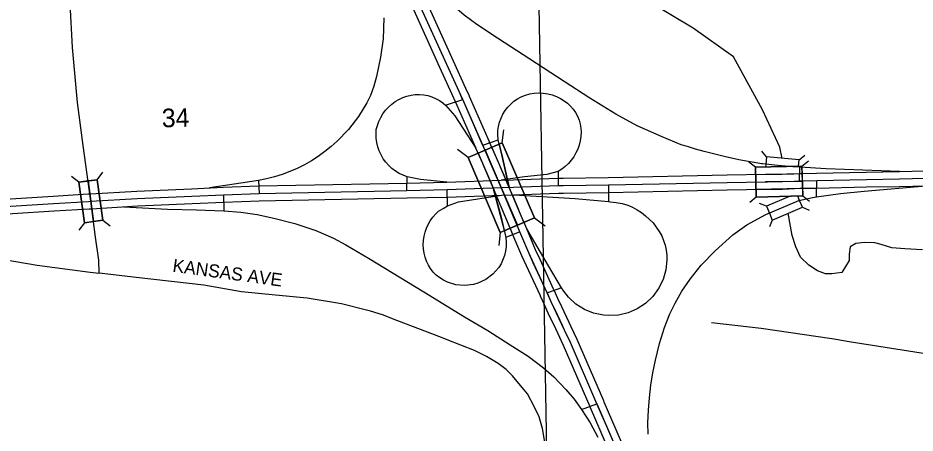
# Model space of a CAD drawing. Extents: x 281.94 to 289.14, y 116.09 to 120.89.
# Drawn here: x 285.132 to 286.097, y 117.681 to 118.127 of the extents above; entities that cross this region are included whole.
import ezdxf

# ---------------------------------------------------------------- set-up
doc = ezdxf.new("R2010")
doc.units = 0
for name, color, linetype in [('tdCiAdjCityStreetCL', 7, 'Continuous'), ('tdCiCityStreetCL', 7, 'Continuous'), ('tdCiCityStreetTxt', 7, 'Continuous'), ('tdCiCorpBndry', 7, 'Continuous'), ('tdCiCorpBndryPart', 7, 'Continuous'), ('tdCiHydroRiver', 7, 'Continuous'), ('tdCiInt', 7, 'Continuous'), ('tdCiIntCL', 7, 'Continuous'), ('tdCiIntRamp', 7, 'Continuous'), ('tdCiIntRampCL', 7, 'Continuous'), ('tdCiPriCL', 7, 'Continuous'), ('tdCiPriDiv', 7, 'Continuous'), ('tdCiPriDivCL', 7, 'Continuous'), ('tdCiSectLine', 7, 'Continuous'), ('tdCiSectNmbr', 7, 'Continuous'), ('tdCiStrucDataInt', 7, 'Continuous'), ('tdCiStrucDataIntRamp', 7, 'Continuous'), ('tdCiStrucDataMuni', 7, 'Continuous')]:
    doc.layers.add(name, color=color, linetype=linetype)

msp = doc.modelspace()

# ---------------------------------------------------------------- linework, layer by layer
at = {"layer": 'tdCiAdjCityStreetCL'}
msp.add_lwpolyline([(285.87779, 117.79917), (285.93129, 117.79315), (286.00727, 117.78207), (286.00754, 117.78203), (286.02595, 117.77891), (286.19916, 117.75172)], dxfattribs=at)
at = {"layer": 'tdCiCityStreetCL'}
for points in [[(285.21935, 117.85226), (285.21906, 117.86639), (285.21533, 117.89099), (285.21033, 117.92955), (285.21032, 117.92965), (285.20191, 117.98939), (285.19595, 118.0356), (285.19066, 118.09462), (285.18812, 118.1422)], [(284.94885, 117.86988), (284.951, 117.87383), (284.95686, 117.8798), (284.96209, 117.88344), (284.96447, 117.88517), (284.96777, 117.8864), (284.97541, 117.88862), (284.98429, 117.88936), (284.99455, 117.8878), (285.01043, 117.88542), (285.06886, 117.87534), (285.15271, 117.8608), (285.20974, 117.85335), (285.21935, 117.85226)], [(285.69882, 117.66854), (285.6961, 117.68531), (285.69257, 117.69802), (285.68747, 117.70824), (285.67983, 117.72255), (285.67621, 117.72701), (285.67243, 117.73167), (285.6638, 117.74203), (285.65689, 117.74869), (285.64826, 117.7551), (285.63569, 117.76274), (285.62286, 117.76916), (285.59352, 117.78075), (285.58752, 117.78304), (285.53951, 117.80146), (285.52397, 117.80763), (285.5112, 117.81132), (285.50523, 117.81305), (285.47983, 117.81922), (285.44284, 117.82563), (285.40881, 117.82859), (285.37231, 117.83229), (285.33199, 117.83956), (285.25894, 117.84776), (285.21935, 117.85226)]]:
    msp.add_lwpolyline(points, dxfattribs=at)
at = {"layer": 'tdCiCorpBndry'}
msp.add_lwpolyline([(285.81018, 117.58382), (285.76521, 117.68749), (285.75462, 117.7119), (285.72604, 117.77774), (285.71977, 117.79109), (285.70553, 117.82143), (285.70112, 117.83122), (285.68125, 117.87407), (285.67171, 117.89675), (285.65172, 117.94419), (285.63185, 117.9898), (285.61025, 118.03882), (285.60634, 118.04751), (285.56352, 118.14174)], dxfattribs=at)
at = {"layer": 'tdCiCorpBndryPart'}
msp.add_lwpolyline([(285.81018, 117.58382), (285.76521, 117.68749), (285.75462, 117.7119), (285.72604, 117.77774), (285.71977, 117.79109), (285.70553, 117.82143), (285.70112, 117.83122), (285.68125, 117.87407), (285.67171, 117.89675), (285.65172, 117.94419), (285.63185, 117.9898), (285.61025, 118.03882), (285.60634, 118.04751), (285.56352, 118.14174)], dxfattribs=at)
at = {"layer": 'tdCiHydroRiver'}
for points in [[(285.95379, 117.97561), (285.9512, 117.98754), (285.93267, 118.02776), (285.90145, 118.08491), (285.85806, 118.11561), (285.8136, 118.14207), (285.77285, 118.15106), (285.73687, 118.15953), (285.68289, 118.16165), (285.6559, 118.16906), (285.63791, 118.19763), (285.62785, 118.22515), (285.61515, 118.2569), (285.60139, 118.29659), (285.59187, 118.31882), (285.57864, 118.34316), (285.5707, 118.35216), (285.54847, 118.36698), (285.5199, 118.37756), (285.49449, 118.38391)], [(286.10466, 117.87747), (286.08561, 117.87853), (286.07185, 117.87958), (286.06021, 117.88329), (286.05333, 117.88488), (286.04222, 117.8854), (286.03322, 117.88435), (286.02687, 117.88064), (286.02581, 117.8727), (286.02581, 117.86582), (286.02581, 117.86582), (286.01787, 117.85312), (286.00729, 117.85154), (286.00041, 117.85154), (285.99194, 117.85471), (285.98242, 117.86106), (285.97342, 117.86953), (285.96866, 117.88064), (285.96443, 117.89281), (285.96015, 117.91661)]]:
    msp.add_lwpolyline(points, dxfattribs=at)
at = {"layer": 'tdCiInt'}
for points in [[(285.66027, 117.94449), (285.64683, 117.97545), (285.64642, 117.97639), (285.63918, 117.99301), (285.63899, 117.99344), (285.61756, 118.04208), (285.61745, 118.04232), (285.61363, 118.05081), (285.60039, 118.07995), (285.57088, 118.14488)], [(285.64313, 117.94388), (285.63216, 117.96906), (285.63175, 117.97), (285.62452, 117.98659), (285.62435, 117.98699), (285.60294, 118.03557), (285.60285, 118.03576), (285.59905, 118.04422), (285.58582, 118.07334), (285.55616, 118.13861)], [(285.65144, 117.95218), (285.6645, 117.95264), (285.71271, 117.95434), (285.71832, 117.95444), (285.76673, 117.95509), (285.89452, 117.95789), (285.93581, 117.95862), (285.93613, 117.95863), (285.93719, 117.95865), (285.95386, 117.95865), (285.96629, 117.9592), (285.96651, 117.95921), (285.97238, 117.95947), (285.99081, 117.9598), (286.04431, 117.961), (286.07984, 117.96154), (286.10779, 117.9622)], [(284.94538, 117.92104), (285.16973, 117.9351), (285.20737, 117.93738), (285.20985, 117.93753), (285.25987, 117.94051), (285.31851, 117.94309), (285.35278, 117.94459), (285.39095, 117.94605), (285.55004, 117.94917), (285.5932, 117.9501), (285.65144, 117.95218)], [(285.65201, 117.93619), (285.66506, 117.93665), (285.71314, 117.93834), (285.71858, 117.93844), (285.76701, 117.93909), (285.89484, 117.9419), (285.93611, 117.94262), (285.93646, 117.94263), (285.93736, 117.94265), (285.95422, 117.94265), (285.96694, 117.94322), (285.96715, 117.94322), (285.97288, 117.94348), (285.99113, 117.94381), (286.04461, 117.945), (286.08015, 117.94554), (286.10827, 117.94621)], [(284.94639, 117.90507), (285.17072, 117.91913), (285.20834, 117.92141), (285.21081, 117.92156), (285.26069, 117.92453), (285.31921, 117.9271), (285.35343, 117.92861), (285.39141, 117.93005), (285.55037, 117.93318), (285.59366, 117.93411), (285.65201, 117.93619)]]:
    msp.add_lwpolyline(points, dxfattribs=at)
at = {"layer": 'tdCiIntCL'}
for points in [[(285.65172, 117.94419), (285.63949, 117.97226), (285.63908, 117.97319), (285.63185, 117.9898), (285.63167, 117.99022), (285.61025, 118.03882), (285.61015, 118.03904), (285.60634, 118.04751), (285.5931, 118.07665), (285.56352, 118.14174)], [(285.65172, 117.94419), (285.66478, 117.94465), (285.71292, 117.94634), (285.71845, 117.94644), (285.76687, 117.94709), (285.89468, 117.94989), (285.93596, 117.95062), (285.9363, 117.95063), (285.93728, 117.95065), (285.95404, 117.95065), (285.96661, 117.95121), (285.96683, 117.95122), (285.97263, 117.95148), (285.99097, 117.9518), (286.04446, 117.953), (286.08, 117.95354), (286.10803, 117.95421)], [(284.94588, 117.91306), (285.17023, 117.92711), (285.20786, 117.9294), (285.21033, 117.92955), (285.26028, 117.93252), (285.31886, 117.9351), (285.35311, 117.9366), (285.39118, 117.93805), (285.5502, 117.94117), (285.59343, 117.9421), (285.65172, 117.94419)]]:
    msp.add_lwpolyline(points, dxfattribs=at)
at = {"layer": 'tdCiIntRamp'}
for points in [[(285.85313, 117.98793), (285.85057, 117.98873), (285.84534, 117.99036), (285.82461, 117.99895), (285.79791, 118.01063), (285.77478, 118.02302), (285.74713, 118.04019), (285.71948, 118.0583), (285.68229, 118.08238), (285.64772, 118.10479), (285.62555, 118.11933), (285.61196, 118.12958), (285.59885, 118.14079), (285.5855, 118.15366), (285.57239, 118.16915), (285.56846, 118.17535), (285.55504, 118.1975), (285.54459, 118.21725), (285.50639, 118.29871)], [(285.52532, 118.12674), (285.52454, 118.10412), (285.52199, 118.08437), (285.51749, 118.06352), (285.51457, 118.05326), (285.51122, 118.04314), (285.50725, 118.03537), (285.49811, 118.02052), (285.48744, 118.00672), (285.47538, 117.99413), (285.46886, 117.98833), (285.46204, 117.98288), (285.45495, 117.9778), (285.4476, 117.97311), (285.44001, 117.96881), (285.4322, 117.96492), (285.42419, 117.96146), (285.41602, 117.95841), (285.40769, 117.95581), (285.39924, 117.95365), (285.39069, 117.95195), (285.3646, 117.94809), (285.33791, 117.94394)], [(285.5932, 117.9501), (285.56489, 117.95308), (285.55045, 117.95586), (285.54606, 117.95748), (285.54184, 117.95953), (285.53785, 117.96198), (285.53412, 117.96481), (285.53068, 117.968), (285.52757, 117.9715), (285.52482, 117.97529), (285.52245, 117.97934), (285.52049, 117.98359), (285.51896, 117.98802), (285.51787, 117.99258), (285.51723, 117.99722), (285.51705, 118.0019), (285.51732, 118.00657), (285.51848, 118.01107), (285.52006, 118.01544), (285.52207, 118.01963), (285.52448, 118.0236), (285.52726, 118.02731), (285.5304, 118.03074), (285.53385, 118.03384), (285.53759, 118.03659), (285.54159, 118.03896), (285.5458, 118.04092), (285.55018, 118.04247), (285.55468, 118.04358), (285.55928, 118.04424), (285.56378, 118.04432), (285.56827, 118.04393), (285.57269, 118.04308), (285.577, 118.04179), (285.58116, 118.04006), (285.58511, 118.03791), (285.58883, 118.03536), (285.5918, 118.03284), (285.60189, 118.02149), (285.62452, 117.98659)], [(285.66027, 117.94449), (285.65219, 117.97948), (285.6484, 117.99575), (285.64796, 118.00085), (285.64813, 118.00547), (285.64878, 118.01004), (285.64989, 118.01453), (285.65146, 118.01887), (285.65347, 118.02303), (285.65589, 118.02697), (285.65871, 118.03063), (285.66188, 118.03398), (285.66539, 118.03699), (285.66918, 118.03963), (285.67323, 118.04186), (285.67776, 118.04359)], [(285.67776, 118.04359), (285.68244, 118.04485), (285.68723, 118.04563), (285.69207, 118.04592), (285.69691, 118.04571), (285.70171, 118.04502), (285.70641, 118.04385), (285.71097, 118.0422), (285.71534, 118.0401), (285.71948, 118.03756), (285.72304, 118.03491), (285.72629, 118.03188), (285.72919, 118.02852), (285.7317, 118.02485), (285.7338, 118.02094), (285.73545, 118.01681), (285.73665, 118.01253), (285.73736, 118.00815), (285.73759, 118.00371), (285.73734, 117.99909), (285.73665, 117.9945), (285.73553, 117.99001), (285.73399, 117.98563), (285.73204, 117.98143), (285.72971, 117.97742), (285.72701, 117.97366), (285.72396, 117.97016), (285.7206, 117.96697), (285.71695, 117.96411), (285.71305, 117.96161), (285.70056, 117.95847), (285.67667, 117.95597), (285.65144, 117.95218)], [(286.07984, 117.96154), (286.00098, 117.96435), (285.97264, 117.96605), (285.96528, 117.96664), (285.94904, 117.96796), (285.93287, 117.96975), (285.93188, 117.96986), (285.91924, 117.97177), (285.90733, 117.97392), (285.89135, 117.97749), (285.8699, 117.98321), (285.8606, 117.9856), (285.85313, 117.98793)], [(285.64313, 117.94388), (285.65142, 117.91376), (285.65679, 117.8908), (285.65709, 117.88586), (285.65695, 117.88092), (285.65637, 117.87601), (285.65535, 117.87117), (285.65157, 117.86244), (285.64902, 117.85842), (285.64274, 117.85127), (285.63512, 117.84557), (285.62649, 117.84158), (285.62191, 117.84027), (285.61247, 117.83913), (285.60299, 117.83995), (285.59389, 117.84272), (285.5896, 117.8448), (285.58555, 117.84732), (285.58179, 117.85023), (285.57835, 117.85353), (285.57566, 117.85718), (285.57333, 117.86108), (285.5714, 117.86518), (285.56986, 117.86945), (285.56875, 117.87385), (285.56807, 117.87834), (285.56782, 117.88287), (285.56801, 117.8874), (285.56864, 117.8919), (285.56971, 117.89631), (285.57119, 117.9006), (285.57308, 117.90472), (285.57536, 117.90865), (285.57801, 117.91233), (285.581, 117.91574), (285.58431, 117.91885), (285.58907, 117.92192), (285.59405, 117.9246), (285.60575, 117.92879), (285.652, 117.93619)], [(285.80978, 117.67936), (285.80945, 117.69164), (285.81007, 117.7051), (285.81115, 117.71854), (285.81268, 117.73193), (285.81466, 117.74526), (285.81756, 117.75876), (285.82199, 117.77689), (285.8272, 117.79386), (285.83318, 117.80872), (285.83858, 117.8199), (285.84591, 117.83302), (285.85478, 117.84575), (285.86655, 117.86079), (285.88159, 117.87642), (285.90069, 117.89358), (285.91592, 117.90438), (285.93618, 117.91519), (285.94569, 117.9192), (285.97186, 117.93023), (285.97355, 117.93062), (285.98459, 117.93312), (285.9908, 117.93423), (286.01641, 117.93788), (286.04206, 117.94048), (286.10827, 117.94621)], [(285.66506, 117.93665), (285.7312, 117.93246), (285.76699, 117.92924), (285.76884, 117.92911), (285.77525, 117.92827), (285.78161, 117.92708), (285.78789, 117.92552), (285.79299, 117.92323), (285.79789, 117.92054), (285.80257, 117.91748), (285.80699, 117.91406), (285.81495, 117.90622), (285.81845, 117.90186), (285.8216, 117.89724), (285.82437, 117.89239), (285.8279, 117.88229), (285.82899, 117.87704), (285.82961, 117.87172), (285.82976, 117.86636), (285.82864, 117.85572), (285.82567, 117.84544), (285.82094, 117.83583), (285.81459, 117.82721), (285.80683, 117.81984), (285.7979, 117.81395), (285.78807, 117.80972), (285.77764, 117.80728), (285.76691, 117.8067), (285.76154, 117.80712), (285.75103, 117.80935), (285.74106, 117.8134), (285.73196, 117.81912), (285.72401, 117.82635), (285.71883, 117.83311), (285.71643, 117.83663), (285.70268, 117.86019), (285.67908, 117.89986)], [(285.24587, 117.92365), (285.29263, 117.92116), (285.32389, 117.92033), (285.35348, 117.91936), (285.37148, 117.91788), (285.38924, 117.91542), (285.40724, 117.91147), (285.42968, 117.9058), (285.45212, 117.89816), (285.47111, 117.89002), (285.48443, 117.88287), (285.50884, 117.86856), (285.56827, 117.83231), (285.61217, 117.80543), (285.63732, 117.79063), (285.66124, 117.77535), (285.68073, 117.76302), (285.69725, 117.75044), (285.7081, 117.74107), (285.72117, 117.72726), (285.73029, 117.7169), (285.73807, 117.70579), (285.74743, 117.6915), (285.75556, 117.67606)]]:
    msp.add_lwpolyline(points, dxfattribs=at)
at = {"layer": 'tdCiIntRampCL'}
for points in [[(285.52532, 118.12674), (285.52454, 118.10412), (285.52199, 118.08437), (285.51749, 118.06352), (285.51457, 118.05326), (285.51122, 118.04314), (285.50725, 118.03537), (285.49811, 118.02052), (285.48744, 118.00672), (285.47538, 117.99413), (285.46886, 117.98833), (285.46204, 117.98288), (285.45495, 117.9778), (285.4476, 117.97311), (285.44001, 117.96881), (285.4322, 117.96492), (285.42419, 117.96146), (285.41602, 117.95841), (285.40769, 117.95581), (285.39924, 117.95365), (285.39069, 117.95195), (285.39118, 117.93805)], [(285.97263, 117.95148), (285.97264, 117.96605), (285.96528, 117.96664), (285.94904, 117.96796), (285.93287, 117.96975), (285.93188, 117.96986), (285.91924, 117.97177), (285.90733, 117.97392), (285.89135, 117.97749), (285.8699, 117.98321), (285.8606, 117.9856), (285.85313, 117.98793), (285.85057, 117.98873), (285.84534, 117.99036), (285.82461, 117.99895), (285.79791, 118.01063), (285.77478, 118.02302), (285.74713, 118.04019), (285.71948, 118.0583), (285.68229, 118.08238), (285.64772, 118.10479), (285.62555, 118.11933), (285.61196, 118.12958)], [(285.5502, 117.94117), (285.55045, 117.95586), (285.54606, 117.95748), (285.54184, 117.95953), (285.53785, 117.96198), (285.53412, 117.96481), (285.53068, 117.968), (285.52757, 117.9715), (285.52482, 117.97529), (285.52245, 117.97934), (285.52049, 117.98359), (285.51896, 117.98802), (285.51787, 117.99258), (285.51723, 117.99722), (285.51705, 118.0019), (285.51732, 118.00657), (285.51848, 118.01107), (285.52006, 118.01544), (285.52207, 118.01963), (285.52448, 118.0236), (285.52726, 118.02731), (285.5304, 118.03074), (285.53385, 118.03384), (285.53759, 118.03659), (285.54159, 118.03896), (285.5458, 118.04092), (285.55017, 118.04247), (285.55468, 118.04358), (285.55928, 118.04424), (285.56378, 118.04432), (285.56827, 118.04393), (285.57269, 118.04308), (285.577, 118.04179), (285.58116, 118.04006), (285.58511, 118.03791), (285.58883, 118.03536), (285.5918, 118.03284), (285.61025, 118.03882)], [(285.63185, 117.9898), (285.6484, 117.99575), (285.64796, 118.00085), (285.64813, 118.00547), (285.64878, 118.01004), (285.64989, 118.01453), (285.65146, 118.01887), (285.65347, 118.02303), (285.65589, 118.02697), (285.65871, 118.03063), (285.66188, 118.03398), (285.66539, 118.03699), (285.66918, 118.03963), (285.67323, 118.04186), (285.67776, 118.04359), (285.68244, 118.04485), (285.68723, 118.04563), (285.69207, 118.04592), (285.69691, 118.04571), (285.70171, 118.04502), (285.70641, 118.04385), (285.71097, 118.0422), (285.71534, 118.0401), (285.71948, 118.03756), (285.72304, 118.03491), (285.72629, 118.03188), (285.72919, 118.02852), (285.7317, 118.02485), (285.7338, 118.02094), (285.73545, 118.01681), (285.73665, 118.01253), (285.73736, 118.00815), (285.73759, 118.00371), (285.73734, 117.99909), (285.73665, 117.9945), (285.73553, 117.99001), (285.73399, 117.98563), (285.73204, 117.98143), (285.72971, 117.97742), (285.72701, 117.97366), (285.72396, 117.97016), (285.7206, 117.96697), (285.71695, 117.96411), (285.71305, 117.96161), (285.71292, 117.94634)], [(285.80978, 117.67936), (285.80945, 117.69164), (285.81007, 117.7051), (285.81115, 117.71854), (285.81268, 117.73193), (285.81466, 117.74526), (285.81756, 117.75876), (285.82199, 117.77689), (285.8272, 117.79386), (285.83318, 117.80872), (285.83858, 117.8199), (285.84591, 117.83302), (285.85478, 117.84575), (285.86655, 117.86079), (285.88159, 117.87642), (285.90069, 117.89358), (285.91592, 117.90439), (285.93618, 117.91519), (285.94569, 117.9192), (285.97186, 117.93023), (285.97355, 117.93062), (285.98459, 117.93312), (285.9908, 117.93423), (285.99097, 117.9518)], [(285.67171, 117.89675), (285.65679, 117.8908), (285.65709, 117.88586), (285.65695, 117.88092), (285.65637, 117.87601), (285.65535, 117.87117), (285.65157, 117.86244), (285.64902, 117.85842), (285.64274, 117.85127), (285.63512, 117.84557), (285.62649, 117.84158), (285.62191, 117.84027), (285.61247, 117.83913), (285.60299, 117.83995), (285.59389, 117.84272), (285.5896, 117.8448), (285.58555, 117.84732), (285.58179, 117.85024), (285.57835, 117.85353), (285.57566, 117.85718), (285.57333, 117.86108), (285.5714, 117.86518), (285.56986, 117.86945), (285.56875, 117.87385), (285.56807, 117.87834), (285.56782, 117.88287), (285.56801, 117.8874), (285.56864, 117.8919), (285.56971, 117.89631), (285.57119, 117.9006), (285.57308, 117.90472), (285.57536, 117.90865), (285.57801, 117.91233), (285.581, 117.91574), (285.58431, 117.91885), (285.58907, 117.92192), (285.59405, 117.9246), (285.59343, 117.9421)], [(285.76687, 117.94709), (285.76699, 117.92924), (285.76884, 117.92911), (285.77525, 117.92827), (285.78161, 117.92708), (285.78789, 117.92552), (285.79299, 117.92323), (285.79789, 117.92054), (285.80257, 117.91748), (285.80699, 117.91406), (285.81495, 117.90622), (285.81845, 117.90186), (285.8216, 117.89724), (285.82437, 117.89239), (285.8279, 117.88229), (285.82899, 117.87704), (285.82961, 117.87172), (285.82976, 117.86636), (285.82864, 117.85572), (285.82567, 117.84544), (285.82094, 117.83583), (285.81459, 117.82721), (285.80683, 117.81984), (285.7979, 117.81395), (285.78807, 117.80972), (285.77764, 117.80728), (285.76691, 117.8067), (285.76154, 117.80712), (285.75103, 117.80935), (285.74106, 117.8134), (285.73196, 117.81912), (285.72401, 117.82635), (285.71883, 117.83311), (285.71643, 117.83663), (285.70234, 117.83165), (285.70112, 117.83122)], [(285.35311, 117.9366), (285.35348, 117.91936), (285.37148, 117.91788), (285.38924, 117.91542), (285.40724, 117.91147), (285.42968, 117.9058), (285.45212, 117.89816), (285.47111, 117.89002), (285.48443, 117.88287), (285.50884, 117.86856), (285.56827, 117.83231), (285.61217, 117.80543), (285.63732, 117.79064), (285.66124, 117.77535), (285.68073, 117.76302), (285.69725, 117.75044), (285.7081, 117.74107), (285.72117, 117.72726), (285.73029, 117.7169), (285.73807, 117.70579), (285.75462, 117.7119)]]:
    msp.add_lwpolyline(points, dxfattribs=at)
at = {"layer": 'tdCiPriCL'}
msp.add_lwpolyline([(285.89663, 117.3851), (285.89405, 117.3909), (285.88051, 117.42219), (285.87255, 117.44058), (285.84937, 117.49489), (285.81018, 117.58382), (285.81004, 117.58415), (285.75516, 117.71067), (285.75462, 117.7119), (285.72604, 117.77774), (285.71977, 117.79109), (285.71748, 117.79597), (285.70957, 117.81282), (285.70542, 117.82166), (285.70134, 117.83073), (285.70112, 117.83122), (285.68612, 117.86358), (285.68125, 117.87407), (285.67171, 117.89675), (285.67168, 117.89681), (285.66404, 117.91494), (285.66272, 117.91807), (285.65191, 117.94372), (285.65172, 117.94419)], dxfattribs=at)
at = {"layer": 'tdCiPriDiv'}
for points in [[(285.88933, 117.38184), (285.88672, 117.38769), (285.87317, 117.41901), (285.8652, 117.43742), (285.84203, 117.49171), (285.80285, 117.58061), (285.8027, 117.58096), (285.74782, 117.70749), (285.74728, 117.70872), (285.71875, 117.77445), (285.71253, 117.78769), (285.71024, 117.79256), (285.70233, 117.80942), (285.69815, 117.81832), (285.69405, 117.82745), (285.69385, 117.8279), (285.67886, 117.86021), (285.67393, 117.87084), (285.66433, 117.89365), (285.66431, 117.8937), (285.65667, 117.91183), (285.65535, 117.91497), (285.64454, 117.94062), (285.64313, 117.94388)], [(285.90394, 117.38836), (285.90137, 117.39412), (285.88785, 117.42536), (285.8799, 117.44374), (285.85671, 117.49808), (285.81751, 117.58702), (285.81738, 117.58733), (285.76249, 117.71385), (285.76196, 117.71509), (285.73333, 117.78104), (285.72701, 117.79449), (285.72472, 117.79937), (285.71681, 117.81622), (285.71269, 117.82499), (285.70864, 117.83401), (285.7084, 117.83455), (285.69337, 117.86694), (285.68857, 117.87731), (285.67908, 117.89986), (285.67906, 117.89992), (285.67142, 117.91805), (285.6701, 117.92118), (285.66442, 117.93464), (285.66027, 117.94449)]]:
    msp.add_lwpolyline(points, dxfattribs=at)
at = {"layer": 'tdCiPriDivCL'}
msp.add_lwpolyline([(285.89663, 117.3851), (285.89405, 117.3909), (285.88051, 117.42219), (285.87255, 117.44058), (285.84937, 117.49489), (285.81018, 117.58382), (285.81004, 117.58415), (285.75516, 117.71067), (285.75462, 117.7119), (285.72604, 117.77774), (285.71977, 117.79109), (285.71748, 117.79597), (285.70957, 117.81282), (285.70542, 117.82166), (285.70134, 117.83073), (285.70112, 117.83122), (285.68612, 117.86358), (285.68125, 117.87407), (285.67171, 117.89675), (285.67168, 117.89681), (285.66404, 117.91494), (285.66272, 117.91807), (285.65191, 117.94372), (285.65172, 117.94419)], dxfattribs=at)
at = {"layer": 'tdCiSectLine'}
msp.add_lwpolyline([(285.67077, 119.30689), (285.68714, 118.43194), (285.70175, 117.57749)], dxfattribs=at)
at = {"layer": 'tdCiStrucDataInt'}
for p, q in [((285.6269, 117.98113), (285.64313, 117.94388)), ((285.6416, 117.98746), (285.66027, 117.94449)), ((285.92533, 117.95843), (285.97532, 117.95952)), ((285.66136, 117.90071), (285.64313, 117.94388)), ((285.6551, 117.89801), (285.64313, 117.94388)), ((285.67606, 117.90703), (285.66027, 117.94449)), ((285.92571, 117.94244), (285.9757, 117.94353))]:
    msp.add_line(p, q, dxfattribs=at)
for points in [[(285.68739, 117.91191), (285.65279, 117.99228), (285.6544, 118.00644)], [(285.65279, 117.99228), (285.63442, 117.98437), (285.61605, 117.97647), (285.60466, 117.98504)], [(285.64954, 117.99088), (285.65219, 117.97948), (285.66027, 117.94449)], [(285.63442, 117.98437), (285.65172, 117.94419), (285.66902, 117.904)], [(285.61605, 117.97647), (285.65065, 117.89609), (285.64904, 117.88193)], [(285.97514, 117.96723), (285.92516, 117.96606), (285.91796, 117.97155)], [(285.97589, 117.93523), (285.97552, 117.95123), (285.97514, 117.96723), (285.98208, 117.97305)], [(285.92516, 117.96606), (285.92553, 117.95006), (285.9259, 117.93407), (285.91897, 117.92825)], [(285.92553, 117.95006), (285.95052, 117.95065), (285.97552, 117.95123)], [(285.9259, 117.93407), (285.97589, 117.93523), (285.98309, 117.92974)], [(285.65065, 117.89609), (285.66902, 117.904), (285.68739, 117.91191), (285.69877, 117.90334)]]:
    msp.add_lwpolyline(points, dxfattribs=at)
for points in [[(285.65279, 117.99228), (285.68739, 117.91191), (285.65065, 117.89609), (285.61605, 117.97647)], [(285.92516, 117.96606), (285.97514, 117.96723), (285.97589, 117.93523), (285.9259, 117.93407)]]:
    msp.add_lwpolyline(points, close=True, dxfattribs=at)
at = {"layer": 'tdCiStrucDataIntRamp'}
for points in [[(285.97209, 117.97392), (285.93704, 117.97715), (285.93192, 117.9833)], [(285.93704, 117.97715), (285.9363, 117.96918), (285.93604, 117.96631)], [(285.97146, 117.96714), (285.97209, 117.97392), (285.97824, 117.97904)], [(285.96239, 117.93492), (285.93691, 117.92418), (285.9295, 117.92719)], [(285.97556, 117.92311), (285.97245, 117.93048), (285.9705, 117.93511)], [(285.93691, 117.92418), (285.94002, 117.91681), (285.94313, 117.90943), (285.94011, 117.90202)], [(285.94313, 117.90943), (285.97556, 117.92311), (285.98297, 117.9201)]]:
    msp.add_lwpolyline(points, dxfattribs=at)
at = {"layer": 'tdCiStrucDataMuni'}
for points in [[(285.21727, 117.9527), (285.20736, 117.95135), (285.19745, 117.94999), (285.18949, 117.95604)], [(285.20736, 117.95135), (285.21033, 117.92955), (285.2133, 117.90775)], [(285.22321, 117.9091), (285.21727, 117.9527), (285.22332, 117.96066)], [(285.19745, 117.94999), (285.2034, 117.9064), (285.19734, 117.89844)], [(285.2034, 117.9064), (285.2133, 117.90775), (285.22321, 117.9091), (285.23117, 117.90305)]]:
    msp.add_lwpolyline(points, dxfattribs=at)
msp.add_lwpolyline([(285.21727, 117.9527), (285.22321, 117.9091), (285.2034, 117.9064), (285.19745, 117.94999)], close=True, dxfattribs=at)

# ---------------------------------------------------------------- texts
at = {"layer": 'tdCiCityStreetTxt'}
msp.add_text('KANSAS AVE', height=0.014, rotation=352.17822, dxfattribs=at).set_placement((285.29762, 117.85393))
at = {"layer": 'tdCiSectNmbr'}
msp.add_text('34', height=0.02, rotation=1.39558, dxfattribs=at).set_placement((285.28682, 118.00894))

doc.saveas('drawing.dxf')
